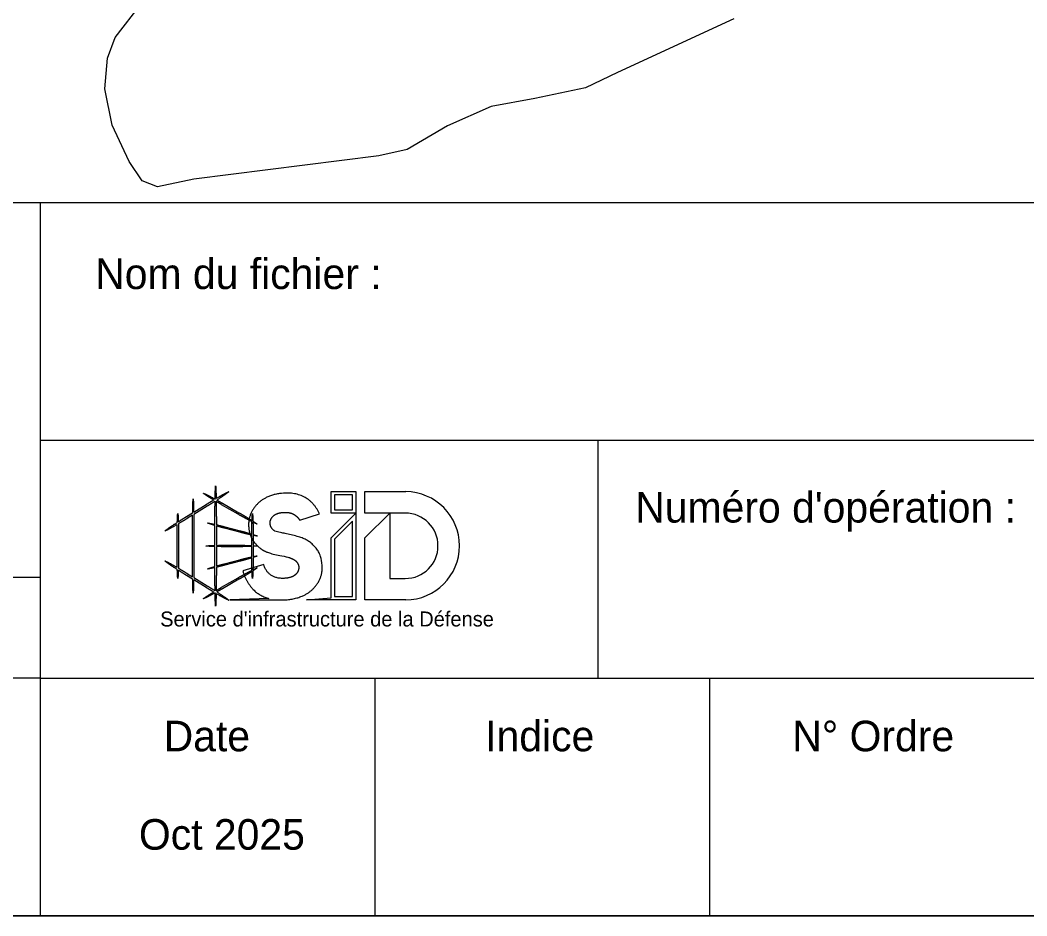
# Model space of a CAD drawing. Extents: x 344013 to 344423, y 298505 to 298795.
# Drawn here: x 344347.76 to 344397.14, y 298504.88 to 298548.82 of the extents above; entities that cross this region are included whole.
import ezdxf

# ---------------------------------------------------------------- set-up
doc = ezdxf.new("R2010")
doc.units = 0
doc.layers.add('DH_CADRE -CARTOUCHE', color=7, linetype='Continuous')
doc.layers.add('TOPO_COURBE NIVEAU', color=7, linetype='Continuous')

msp = doc.modelspace()

# ---------------------------------------------------------------- linework, layer by layer
at = {"layer": 'DH_CADRE -CARTOUCHE'}
for p, q in [((344348.743, 298539.876), (344348.743, 298504.876)), ((344348.743, 298528.209), (344397.985, 298528.209)), ((344376.095, 298528.209), (344376.095, 298516.543)), ((344356.271, 298524.686), (344356.883, 298525.062)), ((344358.451, 298524.584), (344357.642, 298525.049)), ((344357.683, 298525.122), (344358.493, 298524.657)), ((344355.917, 298524.468), (344356.221, 298524.655)), ((344356.936, 298524.975), (344356.274, 298524.567)), ((344361.474, 298524.295), (344362.448, 298524.594)), ((344356.219, 298524.534), (344355.971, 298524.381)), ((344357.312, 298524.082), (344357.312, 298524.374)), ((344357.382, 298524.374), (344357.382, 298524.066)), ((344356.212, 298522.311), (344356.212, 298523.735)), ((344356.281, 298523.735), (344356.281, 298522.311)), ((344357.312, 298523.051), (344357.312, 298524.029)), ((344357.382, 298524.008), (344357.382, 298523.053)), ((344358.533, 298523.7), (344357.786, 298523.895)), ((344357.804, 298523.963), (344358.551, 298523.767)), ((344355.458, 298522.53), (344355.458, 298523.516)), ((344355.527, 298523.516), (344355.527, 298522.53)), ((344359.119, 298523.044), (344359.119, 298523.516)), ((344359.189, 298523.516), (344359.189, 298523.041)), ((344357.312, 298522.017), (344357.312, 298522.995)), ((344357.382, 298522.993), (344357.382, 298522.038)), ((344357.742, 298523.058), (344358.514, 298523.058)), ((344358.514, 298522.988), (344357.742, 298522.988)), ((344359.119, 298522.53), (344359.119, 298523.002)), ((344359.189, 298523.006), (344359.189, 298522.53)), ((344357.786, 298522.151), (344358.533, 298522.347)), ((344358.551, 298522.279), (344357.804, 298522.084)), ((344355.971, 298521.665), (344356.219, 298521.512)), ((344357.312, 298521.672), (344357.312, 298521.964)), ((344357.382, 298521.98), (344357.382, 298521.672)), ((344356.221, 298521.391), (344355.917, 298521.578)), ((344356.883, 298520.984), (344356.271, 298521.36)), ((344356.274, 298521.479), (344356.936, 298521.071)), ((344357.642, 298520.997), (344358.451, 298521.462)), ((344358.493, 298521.389), (344357.683, 298520.924)), ((344359.963, 298520.446), (344358.04, 298520.374)), ((344358.04, 298520.374), (344360.593, 298520.374)), ((344348.743, 298516.543), (344422.906, 298516.543)), ((344365.157, 298516.543), (344365.157, 298504.876)), ((344381.571, 298516.543), (344381.571, 298504.876))]:
    msp.add_line(p, q, dxfattribs=at)
for points in [[(344012.906, 298504.876), (344422.906, 298504.876), (344422.906, 298791.876), (344012.906, 298791.876)], [(344222.906, 298539.876), (344422.906, 298539.876), (344422.906, 298504.876), (344222.906, 298504.876)], [(344363.008, 298525.689), (344364.223, 298525.689), (344364.223, 298524.636), (344363.008, 298524.636)], [(344363.171, 298524.799), (344364.061, 298524.799), (344364.061, 298525.526), (344363.171, 298525.526)], [(344364.223, 298520.374), (344363.008, 298520.374), (344361.798, 298520.374), (344363.008, 298520.475), (344363.008, 298523.42), (344364.223, 298524.636)], [(344364.061, 298524.242), (344363.171, 298523.352), (344363.171, 298520.537), (344364.061, 298520.537)], [(344275.473, 298521.488), (344348.743, 298521.488), (344348.743, 298516.543), (344275.473, 298516.543)]]:
    msp.add_lwpolyline(points, close=True, dxfattribs=at)
for points in [[(344366.65, 298524.636), (344364.668, 298524.636), (344364.668, 298525.689), (344366.67, 298525.689)], [(344366.67, 298520.374), (344364.668, 298520.374), (344364.668, 298523.42), (344365.884, 298524.636), (344365.884, 298521.428), (344366.65, 298521.428)], [(344359.731, 298522.032), (344359.704, 298522.117), (344358.679, 298521.802)]]:
    msp.add_lwpolyline(points, dxfattribs=at)
for radius, start, end in [(2.658, 270.4248, 89.5752), (1.604, 270, 90)]:
    msp.add_arc((344366.65, 298523.032), radius, start, end, dxfattribs=at)
for points, degree in [([(344357.25, 298525.282), (344357.039, 298525.41), (344356.845, 298525.535), (344356.753, 298525.608)], 2), ([(344356.753, 298525.608), (344356.869, 298525.564), (344357.091, 298525.449), (344357.321, 298525.324)], 2), ([(344357.322, 298525.324), (344357.328, 298525.598), (344357.336, 298525.837), (344357.347, 298525.974)], 2), ([(344357.347, 298525.974), (344357.358, 298525.842), (344357.366, 298525.615), (344357.372, 298525.353)], 2), ([(344357.372, 298525.353), (344357.626, 298525.501), (344357.865, 298525.632), (344357.995, 298525.687)], 2), ([(344357.995, 298525.687), (344357.886, 298525.594), (344357.657, 298525.438), (344357.408, 298525.276)], 2), ([(344360.586, 298525.604), (344359.794, 298525.525), (344359.352, 298525.039)], 2), ([(344362.448, 298524.594), (344361.906, 298525.737), (344360.586, 298525.604)], 2), ([(344356.221, 298524.655), (344356.226, 298524.941), (344356.235, 298525.193), (344356.246, 298525.335)], 2), ([(344356.246, 298525.335), (344356.258, 298525.198), (344356.266, 298524.959), (344356.271, 298524.686)], 2), ([(344356.883, 298525.062), (344356.906, 298525.076), (344356.929, 298525.09), (344356.952, 298525.104)], 2), ([(344356.952, 298525.104), (344357.047, 298525.162), (344357.149, 298525.222), (344357.25, 298525.282)], 2), ([(344357.32, 298525.219), (344357.214, 298525.15), (344357.107, 298525.082), (344357.005, 298525.018)], 2), ([(344357.313, 298524.475), (344357.314, 298524.714), (344357.316, 298524.976), (344357.32, 298525.219)], 2), ([(344357.321, 298525.324), (344357.321, 298525.324), (344357.322, 298525.324), (344357.322, 298525.324)], 2), ([(344357.374, 298525.207), (344357.378, 298524.968), (344357.38, 298524.71), (344357.382, 298524.475)], 2), ([(344357.584, 298525.083), (344357.516, 298525.122), (344357.445, 298525.164), (344357.374, 298525.207)], 2), ([(344357.408, 298525.276), (344357.482, 298525.235), (344357.556, 298525.194), (344357.626, 298525.155)], 2), ([(344357.642, 298525.049), (344357.623, 298525.06), (344357.604, 298525.071), (344357.584, 298525.083)], 2), ([(344357.626, 298525.155), (344357.645, 298525.144), (344357.664, 298525.133), (344357.683, 298525.122)], 2), ([(344355.468, 298524.182), (344355.473, 298524.368), (344355.481, 298524.53), (344355.492, 298524.623)], 2), ([(344355.492, 298524.623), (344355.503, 298524.535), (344355.511, 298524.386), (344355.516, 298524.213)], 2), ([(344356.274, 298524.567), (344356.278, 298524.328), (344356.28, 298524.071), (344356.281, 298523.836)], 2), ([(344357.005, 298525.018), (344356.982, 298525.004), (344356.959, 298524.989), (344356.936, 298524.975)], 2), ([(344358.509, 298524.551), (344358.489, 298524.562), (344358.47, 298524.573), (344358.451, 298524.584)], 2), ([(344358.493, 298524.657), (344358.512, 298524.646), (344358.531, 298524.635), (344358.55, 298524.623)], 2), ([(344358.55, 298524.623), (344358.743, 298524.51), (344358.961, 298524.38), (344359.132, 298524.269)], 2), ([(344359.352, 298525.039), (344358.911, 298524.554), (344358.972, 298523.913)], 2), ([(344359.132, 298524.269), (344359.137, 298524.418), (344359.145, 298524.544), (344359.154, 298524.623)], 2), ([(344359.154, 298524.623), (344359.164, 298524.539), (344359.172, 298524.402), (344359.177, 298524.24)], 2), ([(344360.155, 298524.471), (344360.311, 298524.638), (344360.629, 298524.666)], 2), ([(344360.629, 298524.666), (344360.984, 298524.698), (344361.204, 298524.562)], 2), ([(344361.204, 298524.562), (344361.343, 298524.476), (344361.474, 298524.295)], 2), ([(344354.859, 298523.756), (344354.971, 298523.852), (344355.21, 298524.015), (344355.468, 298524.182)], 2), ([(344355.465, 298524.08), (344355.217, 298523.937), (344354.986, 298523.81), (344354.859, 298523.756)], 2), ([(344355.458, 298523.586), (344355.459, 298523.745), (344355.461, 298523.918), (344355.465, 298524.08)], 2), ([(344355.516, 298524.213), (344355.628, 298524.286), (344355.742, 298524.358), (344355.849, 298524.425)], 2), ([(344355.902, 298524.339), (344355.78, 298524.265), (344355.648, 298524.187), (344355.519, 298524.112)], 2), ([(344355.519, 298524.112), (344355.523, 298523.941), (344355.526, 298523.755), (344355.527, 298523.586)], 2), ([(344355.849, 298524.425), (344355.872, 298524.44), (344355.895, 298524.454), (344355.917, 298524.468)], 2), ([(344355.971, 298524.381), (344355.948, 298524.367), (344355.925, 298524.353), (344355.902, 298524.339)], 2), ([(344356.212, 298523.836), (344356.213, 298524.06), (344356.215, 298524.304), (344356.219, 298524.534)], 2), ([(344357.312, 298524.029), (344357.161, 298524.074), (344357.028, 298524.118), (344356.956, 298524.149)], 2), ([(344356.956, 298524.149), (344357.032, 298524.141), (344357.164, 298524.115), (344357.312, 298524.082)], 2), ([(344357.312, 298524.374), (344357.313, 298524.407), (344357.313, 298524.441), (344357.313, 298524.475)], 2), ([(344357.382, 298524.475), (344357.382, 298524.441), (344357.382, 298524.407), (344357.382, 298524.374)], 2), ([(344357.382, 298524.066), (344357.504, 298524.038), (344357.633, 298524.006), (344357.751, 298523.976)], 2), ([(344359.13, 298524.215), (344358.945, 298524.309), (344358.712, 298524.437), (344358.509, 298524.551)], 2), ([(344359.12, 298523.604), (344359.121, 298523.803), (344359.124, 298524.024), (344359.13, 298524.215)], 2), ([(344359.177, 298524.24), (344359.263, 298524.184), (344359.335, 298524.135), (344359.381, 298524.098)], 2), ([(344359.381, 298524.098), (344359.331, 298524.117), (344359.261, 298524.15), (344359.178, 298524.19)], 2), ([(344359.178, 298524.19), (344359.184, 298523.999), (344359.187, 298523.781), (344359.188, 298523.586)], 2), ([(344360.021, 298524.106), (344359.999, 298524.304), (344360.155, 298524.471)], 2), ([(344360.258, 298523.746), (344360.044, 298523.889), (344360.021, 298524.106)], 2), ([(344355.458, 298523.516), (344355.458, 298523.539), (344355.458, 298523.562), (344355.458, 298523.586)], 2), ([(344355.527, 298523.586), (344355.527, 298523.562), (344355.527, 298523.539), (344355.527, 298523.516)], 2), ([(344356.212, 298523.735), (344356.212, 298523.768), (344356.212, 298523.802), (344356.212, 298523.836)], 2), ([(344356.281, 298523.836), (344356.281, 298523.802), (344356.281, 298523.768), (344356.281, 298523.735)], 2), ([(344357.733, 298523.91), (344357.62, 298523.94), (344357.498, 298523.975), (344357.382, 298524.008)], 2), ([(344357.786, 298523.895), (344357.769, 298523.9), (344357.751, 298523.905), (344357.733, 298523.91)], 2), ([(344357.751, 298523.976), (344357.769, 298523.972), (344357.787, 298523.967), (344357.804, 298523.963)], 2), ([(344358.586, 298523.686), (344358.569, 298523.691), (344358.551, 298523.695), (344358.533, 298523.7)], 2), ([(344358.551, 298523.767), (344358.568, 298523.762), (344358.586, 298523.757), (344358.604, 298523.752)], 2), ([(344359.12, 298523.56), (344358.957, 298523.594), (344358.76, 298523.642), (344358.586, 298523.686)], 2), ([(344358.604, 298523.752), (344358.773, 298523.707), (344358.963, 298523.653), (344359.12, 298523.604)], 2), ([(344358.972, 298523.913), (344359.012, 298523.491), (344359.261, 298523.182)], 2), ([(344359.188, 298523.586), (344359.188, 298523.585), (344359.188, 298523.584), (344359.188, 298523.582)], 2), ([(344359.188, 298523.582), (344359.269, 298523.556), (344359.337, 298523.533), (344359.381, 298523.513)], 2), ([(344362.576, 298522.073), (344362.567, 298522.245), (344362.483, 298522.551), (344362.407, 298522.736), (344362.283, 298522.913), (344362.111, 298523.094), (344361.96, 298523.226), (344361.786, 298523.329), (344361.599, 298523.418), (344361.354, 298523.496), (344361.045, 298523.57), (344360.748, 298523.638), (344360.552, 298523.677), (344360.311, 298523.719), (344360.258, 298523.746)], 3), ([(344359.119, 298523.516), (344359.119, 298523.53), (344359.119, 298523.545), (344359.12, 298523.56)], 2), ([(344359.381, 298523.513), (344359.335, 298523.518), (344359.268, 298523.529), (344359.189, 298523.545)], 2), ([(344359.189, 298523.545), (344359.189, 298523.535), (344359.189, 298523.526), (344359.189, 298523.516)], 2), ([(344359.261, 298523.182), (344359.51, 298522.873), (344359.827, 298522.738)], 2), ([(344356.874, 298523.023), (344356.962, 298523.037), (344357.129, 298523.045), (344357.312, 298523.051)], 2), ([(344357.312, 298522.995), (344357.129, 298523.001), (344356.962, 298523.009), (344356.874, 298523.023)], 2), ([(344357.382, 298523.053), (344357.484, 298523.055), (344357.589, 298523.057), (344357.687, 298523.057)], 2), ([(344357.687, 298522.989), (344357.589, 298522.99), (344357.484, 298522.991), (344357.382, 298522.993)], 2), ([(344357.687, 298523.057), (344357.705, 298523.058), (344357.724, 298523.058), (344357.742, 298523.058)], 2), ([(344357.742, 298522.988), (344357.724, 298522.988), (344357.705, 298522.989), (344357.687, 298522.989)], 2), ([(344358.514, 298523.058), (344358.532, 298523.058), (344358.55, 298523.058), (344358.569, 298523.057)], 2), ([(344358.569, 298522.989), (344358.55, 298522.989), (344358.532, 298522.988), (344358.514, 298522.988)], 2), ([(344358.569, 298523.057), (344358.749, 298523.056), (344358.953, 298523.052), (344359.119, 298523.044)], 2), ([(344359.119, 298523.002), (344358.953, 298522.994), (344358.749, 298522.99), (344358.569, 298522.989)], 2), ([(344359.189, 298523.041), (344359.268, 298523.036), (344359.335, 298523.03), (344359.381, 298523.023)], 2), ([(344359.381, 298523.023), (344359.335, 298523.016), (344359.268, 298523.01), (344359.189, 298523.006)], 2), ([(344359.827, 298522.738), (344359.866, 298522.722), (344359.968, 298522.684), (344360.242, 298522.607), (344360.565, 298522.545), (344360.909, 298522.477), (344360.943, 298522.46)], 3), ([(344355.468, 298521.864), (344355.21, 298522.032), (344354.971, 298522.195), (344354.859, 298522.29)], 2), ([(344354.859, 298522.29), (344354.986, 298522.236), (344355.217, 298522.109), (344355.465, 298521.966)], 2), ([(344355.458, 298522.46), (344355.458, 298522.484), (344355.458, 298522.507), (344355.458, 298522.53)], 2), ([(344355.465, 298521.966), (344355.461, 298522.128), (344355.459, 298522.302), (344355.458, 298522.46)], 2), ([(344355.527, 298522.46), (344355.526, 298522.291), (344355.523, 298522.105), (344355.519, 298521.935)], 2), ([(344355.527, 298522.53), (344355.527, 298522.507), (344355.527, 298522.484), (344355.527, 298522.46)], 2), ([(344356.212, 298522.21), (344356.212, 298522.244), (344356.212, 298522.278), (344356.212, 298522.311)], 2), ([(344356.219, 298521.512), (344356.215, 298521.742), (344356.213, 298521.986), (344356.212, 298522.21)], 2), ([(344356.281, 298522.21), (344356.28, 298521.975), (344356.278, 298521.718), (344356.274, 298521.479)], 2), ([(344356.281, 298522.311), (344356.281, 298522.278), (344356.281, 298522.244), (344356.281, 298522.21)], 2), ([(344357.382, 298522.038), (344357.498, 298522.072), (344357.62, 298522.106), (344357.733, 298522.136)], 2), ([(344357.733, 298522.136), (344357.751, 298522.141), (344357.769, 298522.146), (344357.786, 298522.151)], 2), ([(344358.533, 298522.347), (344358.551, 298522.351), (344358.569, 298522.356), (344358.586, 298522.36)], 2), ([(344358.604, 298522.294), (344358.586, 298522.289), (344358.568, 298522.284), (344358.551, 298522.279)], 2), ([(344358.586, 298522.36), (344358.76, 298522.404), (344358.957, 298522.452), (344359.12, 298522.486)], 2), ([(344359.12, 298522.442), (344358.963, 298522.393), (344358.773, 298522.339), (344358.604, 298522.294)], 2), ([(344359.12, 298522.486), (344359.119, 298522.501), (344359.119, 298522.516), (344359.119, 298522.53)], 2), ([(344359.13, 298521.832), (344359.124, 298522.023), (344359.121, 298522.243), (344359.12, 298522.442)], 2), ([(344359.188, 298522.46), (344359.187, 298522.265), (344359.184, 298522.047), (344359.178, 298521.856)], 2), ([(344359.381, 298522.533), (344359.337, 298522.514), (344359.269, 298522.49), (344359.188, 298522.464)], 2), ([(344359.188, 298522.464), (344359.188, 298522.463), (344359.188, 298522.461), (344359.188, 298522.46)], 2), ([(344359.189, 298522.501), (344359.268, 298522.517), (344359.335, 298522.528), (344359.381, 298522.533)], 2), ([(344359.189, 298522.53), (344359.189, 298522.521), (344359.189, 298522.511), (344359.189, 298522.501)], 2), ([(344360.943, 298522.46), (344361.188, 298522.375), (344361.274, 298522.293)], 2), ([(344361.274, 298522.293), (344361.415, 298522.158), (344361.425, 298521.998)], 2), ([(344355.492, 298521.423), (344355.481, 298521.517), (344355.473, 298521.678), (344355.468, 298521.864)], 2), ([(344355.516, 298521.833), (344355.511, 298521.66), (344355.503, 298521.511), (344355.492, 298521.423)], 2), ([(344355.849, 298521.621), (344355.742, 298521.688), (344355.628, 298521.761), (344355.516, 298521.833)], 2), ([(344355.519, 298521.935), (344355.648, 298521.859), (344355.78, 298521.781), (344355.902, 298521.707)], 2), ([(344355.917, 298521.578), (344355.895, 298521.592), (344355.872, 298521.607), (344355.849, 298521.621)], 2), ([(344355.902, 298521.707), (344355.925, 298521.693), (344355.948, 298521.679), (344355.971, 298521.665)], 2), ([(344356.956, 298521.897), (344357.028, 298521.929), (344357.161, 298521.972), (344357.312, 298522.017)], 2), ([(344357.312, 298521.964), (344357.164, 298521.931), (344357.032, 298521.905), (344356.956, 298521.897)], 2), ([(344357.313, 298521.571), (344357.313, 298521.605), (344357.313, 298521.639), (344357.312, 298521.672)], 2), ([(344357.751, 298522.07), (344357.633, 298522.04), (344357.504, 298522.008), (344357.382, 298521.98)], 2), ([(344357.382, 298521.672), (344357.382, 298521.639), (344357.382, 298521.605), (344357.382, 298521.571)], 2), ([(344357.804, 298522.084), (344357.787, 298522.079), (344357.769, 298522.075), (344357.751, 298522.07)], 2), ([(344358.509, 298521.495), (344358.712, 298521.609), (344358.945, 298521.737), (344359.13, 298521.832)], 2), ([(344359.132, 298521.777), (344358.961, 298521.667), (344358.743, 298521.536), (344358.55, 298521.423)], 2), ([(344358.679, 298521.802), (344359.026, 298520.695), (344359.963, 298520.446)], 2), ([(344359.154, 298521.423), (344359.145, 298521.502), (344359.137, 298521.628), (344359.132, 298521.777)], 2), ([(344359.177, 298521.806), (344359.172, 298521.645), (344359.164, 298521.507), (344359.154, 298521.423)], 2), ([(344359.381, 298521.949), (344359.335, 298521.912), (344359.263, 298521.862), (344359.177, 298521.806)], 2), ([(344359.178, 298521.856), (344359.261, 298521.897), (344359.331, 298521.929), (344359.381, 298521.949)], 2), ([(344360.707, 298521.435), (344359.987, 298521.398), (344359.731, 298522.032)], 2), ([(344361.26, 298521.614), (344361.081, 298521.453), (344360.707, 298521.435)], 2), ([(344361.425, 298521.998), (344361.439, 298521.775), (344361.26, 298521.614)], 2), ([(344362.128, 298520.923), (344362.613, 298521.416), (344362.576, 298522.073)], 2), ([(344356.246, 298520.712), (344356.235, 298520.853), (344356.226, 298521.105), (344356.221, 298521.391)], 2), ([(344356.271, 298521.36), (344356.266, 298521.087), (344356.258, 298520.848), (344356.246, 298520.712)], 2), ([(344357.32, 298520.827), (344357.316, 298521.07), (344357.314, 298521.332), (344357.313, 298521.571)], 2), ([(344357.382, 298521.571), (344357.38, 298521.336), (344357.378, 298521.078), (344357.374, 298520.839)], 2), ([(344358.451, 298521.462), (344358.47, 298521.473), (344358.489, 298521.484), (344358.509, 298521.495)], 2), ([(344358.55, 298521.423), (344358.531, 298521.412), (344358.512, 298521.4), (344358.493, 298521.389)], 2), ([(344356.753, 298520.438), (344356.845, 298520.512), (344357.039, 298520.636), (344357.25, 298520.764)], 2), ([(344357.321, 298520.722), (344357.091, 298520.597), (344356.869, 298520.483), (344356.753, 298520.438)], 2), ([(344356.952, 298520.942), (344356.929, 298520.956), (344356.906, 298520.97), (344356.883, 298520.984)], 2), ([(344356.936, 298521.071), (344356.959, 298521.057), (344356.982, 298521.042), (344357.005, 298521.028)], 2), ([(344357.25, 298520.764), (344357.149, 298520.824), (344357.047, 298520.884), (344356.952, 298520.942)], 2), ([(344357.005, 298521.028), (344357.107, 298520.964), (344357.214, 298520.896), (344357.32, 298520.827)], 2), ([(344357.322, 298520.722), (344357.322, 298520.722), (344357.321, 298520.722), (344357.321, 298520.722)], 2), ([(344357.347, 298520.073), (344357.336, 298520.209), (344357.328, 298520.448), (344357.322, 298520.722)], 2), ([(344357.372, 298520.693), (344357.366, 298520.431), (344357.358, 298520.204), (344357.347, 298520.073)], 2), ([(344357.995, 298520.359), (344357.865, 298520.414), (344357.626, 298520.546), (344357.372, 298520.693)], 2), ([(344357.374, 298520.839), (344357.445, 298520.882), (344357.516, 298520.924), (344357.584, 298520.963)], 2), ([(344357.626, 298520.891), (344357.556, 298520.852), (344357.482, 298520.811), (344357.408, 298520.77)], 2), ([(344357.408, 298520.77), (344357.657, 298520.608), (344357.886, 298520.452), (344357.995, 298520.359)], 2), ([(344357.584, 298520.963), (344357.604, 298520.975), (344357.623, 298520.986), (344357.642, 298520.997)], 2), ([(344357.683, 298520.924), (344357.664, 298520.913), (344357.645, 298520.902), (344357.626, 298520.891)], 2), ([(344360.729, 298520.379), (344361.643, 298520.431), (344362.128, 298520.923)], 2), ([(344360.593, 298520.374), (344360.66, 298520.375), (344360.729, 298520.379)], 2)]:
    msp.add_open_spline(points, degree=degree, dxfattribs=at)
at = {"layer": 'TOPO_COURBE NIVEAU'}
msp.add_lwpolyline([(344382.767, 298548.891), (344377.062, 298546.251), (344375.486, 298545.509), (344373, 298544.972), (344370.858, 298544.578), (344368.72, 298543.633), (344366.735, 298542.482), (344365.357, 298542.158), (344356.281, 298541.012), (344354.495, 298540.641), (344353.746, 298540.932), (344353.101, 298541.891), (344352.267, 298543.668), (344351.919, 298545.445), (344352.036, 298546.964), (344352.414, 298547.972), (344355.001, 298551.319)], dxfattribs=at)

# ---------------------------------------------------------------- texts
at = {"layer": 'DH_CADRE -CARTOUCHE'}
for s, height, p in [('Nom du fichier :', 1.5, (344351.441, 298535.629)), ("Numéro d'opération :", 1.5, (344377.93, 298524.172)), ("Service d'infrastructure de la Défense", 0.73546, (344354.627, 298519.074)), ('DUBOIS SANDRINE', 0.001, (344348.73, 298516.543)), ('DUBOIS SANDRINE', 0.001, (344348.73, 298516.543)), ('Date', 1.5, (344354.799, 298512.95)), ('Indice', 1.5, (344370.569, 298512.95)), ('N° Ordre', 1.5, (344385.634, 298512.95)), ('Oct 2025', 1.5, (344353.584, 298508.123))]:
    msp.add_text(s, height=height, dxfattribs=at).set_placement(p)

doc.saveas('drawing.dxf')
